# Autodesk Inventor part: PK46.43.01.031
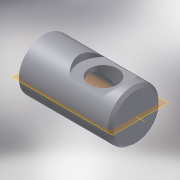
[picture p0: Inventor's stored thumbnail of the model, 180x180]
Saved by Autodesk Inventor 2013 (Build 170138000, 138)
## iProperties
Shininess: 64.0
Length Units: 11269
Angle Units: 11279
Time Units: 11290
Mass Units: 11283
Length Display Precision: 3
Angle Display Precision: 2
Compacted: True
Part Number: PK46.43.01.031
Document SubType Name: Modeling
Created: 2004-12
Material: Сталь низкоуглеродистая
Designer: ELarisa
Manufacturer: Standard
Standards Organization: Custom
Density: 7.86 g/cm^3
Density: 0.0
Volumn: 0.0
Area: 0.0
PropertySet Name: Model Information
Control State: 0
Master: False
Checked Out: False
Checked Out Date: 2008-10-09
Last Check In Date: 2008-10-09
Author: ELarisa
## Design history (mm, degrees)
sketch "Эскиз1"
  geometry: L1 (-35.076, -2.38)-(-35.076, 15.62); L2 (-35.076, 15.62)-(29.924, 15.62); L3 (29.924, 15.62)-(29.924, -2.38); L4 (29.924, -2.38)-(-35.076, -2.38); L5 (-35.076, 7.62)-(18.924, 7.62); L6 (18.924, 7.62)-(24.698, -2.38)
  constraints: 12 end point, 2 parallel, 2 point on line, 1 perpendicular, 1 vertical
  dimensions: "d0" = 65 distance of L3.end L1.start; "d1" = 18 distance of L2.end L3.end; "d3" = 10 distance between parallel lines of L4 L5; "d4" = 120 deg angle of L6 L5; "d6" = 54 distance of L5.start L5.end
revolve "Вращение1" sketch "Эскиз1" stored, may be unused: angle "d7" = 90 deg
node "РабОсь1"
node "РабПлоскость1"
sketch "Эскиз2"
  geometry: L1 (-48.076, -2.38)-(42.924, -2.38) reference; L2 (-35.076, -18.88)-(-35.076, 14.12) reference; L3 (29.924, -20.38)-(29.924, 15.62) reference; L4 (-35.076, -20.38)-(29.924, -20.38) reference; L5 (-35.076, -20.38)-(-35.076, 15.62) reference; 1 further point
  dimensions: "d9" = 0 distance from line of L1 point (6.924, -2.38); "d21" = 42 distance from line of L5 point (6.924, -2.38)
hole "Отверстие1" sketch "Эскиз2" diameter "d11" = 20; stored, may be unused: countersink angle "d15" = 82 deg, drill point angle "d17" = 118 deg; dims "d12" = 6, "d13" = 34, "d14" = 5, "d16" = 18
chamfer "Фаска1" distance "d18" = 2; stored, may be unused: second distance "d19" = 2, angle "d20" = 45 deg
body "Solid1"
other parameters: "d8" = 18
